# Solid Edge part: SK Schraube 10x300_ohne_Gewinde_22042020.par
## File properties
Author: fknapp
Template: Normal.par
Last saved by: fknapp
Revision: 28
Application: Solid Edge
Username: fknapp
Material: Aluminium
Genauigkeit: 0,99
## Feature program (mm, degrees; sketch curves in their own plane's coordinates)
sketch for "unnamed RevolvedProtrusion 1" plane through (0, 0, 0) normal (0, 0, 1) x-axis (1, 0, 0)
  line (0, 54) -> (9, 54)
  line (9, 54) -> (9, 53)
  line (9, 53) -> (5, 49)
  line (5, 49) -> (5, 46.3)
  line (5, 46.3) -> (4.7548, 46.3)
  arc centre (4.7548, 44.6952) radius 1.6048 from (4.7548, 46.3) to (3.15, 44.6952) ccw
  line (3.15, 44.6952) -> (3.15, 42)
  line (3.15, 42) -> (5, 42)
  line (5, -233) -> (5, 42)
  line (0.5, -246) -> (5, -233)
  line (0, -246) -> (0.5, -246)
revolve "unnamed RevolvedProtrusion 1" add full turn 360 deg about sketch line (0, 54) -> (0, -246)
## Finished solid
Body 1: solid body, 11 faces, 10 edges, 0 vertices.
  Faces by surface: cylinder 4, plane 4, cone 2, torus 1
  Edges by curve: circle 10
Bounding box of the edges (mm; curved faces can reach further): 18.000 x 300.000 x 18.000, from (-9, -246, -9) to (9, 54, 9).
Cylindrical faces by radius (mm): R3.15 x1, R5 x2, R9 x1
Conical faces (half-angle, radius in mm at the cone's reference point): 19.0935 deg R5 x1, 45 deg R9 x1
Toroidal faces (ring radius, tube radius in mm): R4.7548 r1.6048 x1
Planar faces by outward normal: +y 2, -y 2
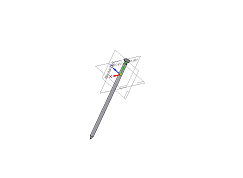
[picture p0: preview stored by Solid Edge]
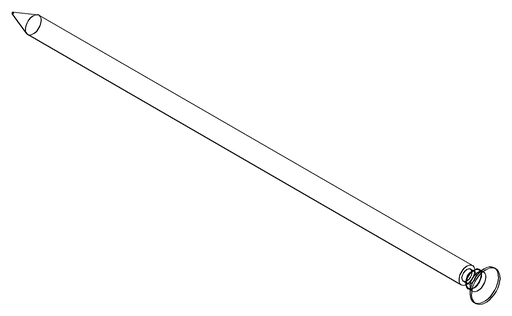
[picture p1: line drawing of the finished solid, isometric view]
